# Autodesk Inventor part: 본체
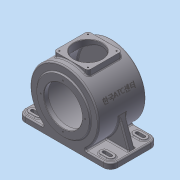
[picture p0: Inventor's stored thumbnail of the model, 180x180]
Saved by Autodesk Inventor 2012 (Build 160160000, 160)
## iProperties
Created: 2015-06
Part Number: 본체
Material: 알루미늄-6061
Document SubType Name: Modeling
Designer: Administrator
Density: 2.71 g/cm^3
Mass: 3293.83 g
Surface Area: 2306.13 cm^2
Volume: 1215.43 cm^3
Author: Administrator
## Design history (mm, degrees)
sketch "스케치1"
  geometry: C1 r 85 at (0, 0); 1 further point
  constraints: 1 centre point, 1 coincident
  dimensions: "d0" = 170 diameter of C1
extrude "돌출1" new body sketch "스케치1" stored distance "d1" = 118; taper "d2" = 0 deg
feature "쉘1" dims "d4" = 8
node "작업 평면11"
sketch "스케치3"
  geometry: C1 r 65 at (0, 0); 1 further point
  constraints: 1 centre point, 1 coincident
  dimensions: "d8" = 130 diameter of C1
sketch "스케치4"
  geometry: C1 r 31 at (0, 0); 1 further point
  constraints: 1 centre point, 1 coincident
  dimensions: "d20" = 62 diameter of C1
extrude "돌출4" join sketch "스케치4" distance "d21" = 3.5; taper "d22" = 0 deg
feature "면 기울기1" dims angle "d41" = 25 deg
node "작업 평면2"
  node "작업 평면1"
sketch "스케치5"
  geometry: L1 (-35.5, 42.5)-(35.5, 42.5); L2 (42.5, 35.5)-(42.5, -35.5); L3 (35.5, -42.5)-(-35.5, -42.5); L4 (-42.5, -35.5)-(-42.5, 35.5); L5 (-42.5, -42.5)-(42.5, 42.5); A1 r 7 centre (-35.5, 35.5) between (-35.5, 42.5) and (-42.5, 35.5); A2 r 7 centre (35.5, 35.5) between (42.5, 35.5) and (35.5, 42.5); A3 r 7 centre (35.5, -35.5) between (35.5, -42.5) and (42.5, -35.5); A4 r 7 centre (-35.5, -35.5) between (-42.5, -35.5) and (-35.5, -42.5); 4 further points
  constraints: 10 end point, 8 point on circle, 8 point on line, 8 tangent, 4 centre point, 3 equal radius, 2 parallel, 1 coincident, 1 horizontal, 1 midpoint, 1 perpendicular
  dimensions: "d44" = 85 distance of point (42.5, -42.5) L5.start; "d45" = 85 distance of L5.start point (-42.5, 42.5); "d46" = 7 radius of A1
extrude "돌출5" join sketch "스케치5" stored distance "d47" = 3.5; taper "d48" = 0 deg
sketch "스케치6"
  geometry: C1 r 35 at (0, 0); 1 further point
  constraints: 1 centre point, 1 coincident
  dimensions: "d49" = 70 diameter of C1
extrude "돌출6" cut sketch "스케치6" stored distance "d50" = 3.5; taper "d51" = 0 deg
sketch "스케치7"
  geometry: A1 r 7 centre (-35.5, 35.5) between (-35.5, 42.5) and (-42.5, 35.5) reference; A2 r 7 centre (-35.5, -35.5) between (-42.5, -35.5) and (-35.5, -42.5) reference; A3 r 7 centre (35.5, -35.5) between (35.5, -42.5) and (42.5, -35.5) reference; A4 r 7 centre (35.5, 35.5) between (42.5, 35.5) and (35.5, 42.5) reference; 5 further points
  constraints: 4 coincident
  dimensions: "d52" = 71 distance of point (35.5, 35.5) point (-35.5, 35.5) (derived); "d53" = 71 distance of point (-35.5, -35.5) point (-35.5, 35.5) (derived)
hole "구멍4" sketch "스케치7" at (-35.5, 35.5), (35.5, 35.5), (35.5, -35.5), (-35.5, -35.5) diameter "d54" = 3.242; stored, may be unused: countersink angle "d58" = 90 deg, drill point angle "d60" = 118 deg; dims "d55" = 10, "d56" = 4, "d57" = 2, "d59" = 13
node "작업 평면9"
node "작업 평면3"
node "작업 평면12"
sketch "스케치11"
  geometry: L1 (-59, -71)-(59, -71); L2 (59, -71)-(59, -85); L3 (59, -85)-(-59, -85); L4 (-59, -85)-(-59, -71); 2 further points
  constraints: 8 end point, 2 parallel, 1 horizontal, 1 midpoint, 1 perpendicular
  dimensions: "d83" = 14 distance of L1.end L2.end; "d84" = 118 distance of L2.end L3.end; "d98" = 85 distance from line of L3 point (0, 0)
extrude "돌출9" join sketch "스케치11" stored distance "d86" = 10; taper "d87" = 0 deg
sketch "스케치13"
  geometry: C1 r 65 at (0, 0); 1 further point
  constraints: 1 centre point, 1 coincident
  dimensions: "d101" = 130 diameter of C1
extrude "돌출13" join sketch "스케치13" distance "d102" = 3; taper "d103" = 0 deg
sketch "스케치8"
  geometry: 5 further points
  dimensions: "d63" = 110 distance of point (0, 55) point (0, -55); "d64" = 110 distance of point (55, 0) point (-55, 0); "d104" = 55 distance of point (0, 0) point (55, 0); "d105" = 55 distance of point (0, 55) point (0, 0)
hole "구멍5" sketch "스케치8" at (0, 55), (-55, 0), (55, 0), (0, -55) diameter "d65" = 3.242; stored, may be unused: countersink angle "d69" = 90 deg, drill point angle "d71" = 118 deg; dims "d66" = 10, "d67" = 4, "d68" = 2, "d70" = 11
extrude "돌출11" join sketch "스케치3" distance "d90" = 13; taper "d91" = 0 deg
node "작업 평면13"
sketch "스케치12"
  geometry: L1 (59, -71)-(-59, -71); L2 (-59, -71)-(-59, -85); L3 (-59, -85)-(59, -85); L4 (59, -85)-(59, -71); 2 further points
  constraints: 8 end point, 2 parallel, 1 horizontal, 1 midpoint, 1 perpendicular, 1 vertical alignment
  dimensions: "d93" = 118 distance of L2.end L3.end; "d94" = 14 distance of L3.end L1.start; "d95" = 85 distance from line of L3 point (0, 0)
extrude "돌출12" join sketch "스케치12" stored distance "d96" = 13; taper "d97" = 0 deg
fillet "모깎기2" dims "d107" = 18
sketch "스케치14"
  geometry: L1 (-34, 9)-(-18, 9); L2 (-18, 27)-(-34, 27); A1 r 9 centre (-18, 18) between (-18, 9) and (-18, 27); A2 r 9 centre (-34, 18) between (-34, 27) and (-34, 9); A3 r 18 centre (-18, 18) between (-18, 0) and (0, 18) reference; 1 further point
  constraints: 4 end point, 4 point on circle, 4 tangent, 2 centre point, 1 coincident, 1 horizontal, 1 parallel
  dimensions: "d108" = 18 distance between parallel lines of L1 L2; "d109" = 16 distance of A2.centre A1.centre
extrude "돌출14" join sketch "스케치14" distance "d110" = 3; taper "d111" = 0 deg
sketch "스케치15"
  geometry: L1 (-34, 27)-(-18, 27) reference; L2 (-18, 9)-(-34, 9) reference; L3 (-18, 14)-(-34, 14); L4 (-34, 22)-(-18, 22); A1 r 9 centre (-18, 18) between (-18, 9) and (-18, 27) reference; A2 r 9 centre (-34, 18) between (-34, 27) and (-34, 9) reference; A3 r 4 centre (-18, 18) between (-18, 14) and (-18, 22); A4 r 4 centre (-34, 18) between (-34, 22) and (-34, 14); 1 further point
  constraints: 4 end point, 4 point on circle, 2 centre point, 3 other
  dimensions: "d112" = 24 dimension on A3 A4
extrude "돌출15" cut sketch "스케치15" stored distance "d113" = 3; taper "d114" = 0 deg
fillet "모깎기6" dims "d142" = 3
sketch "스케치16"
  geometry: L1 (-109, -71)-(-84.87, -4.703); L2 (-115, -74)-(-115, -85) reference; L3 (-106, -71)-(-97, -71) reference; A1 r 85 centre (0, 0) between (46.733, -71) and (-46.733, -71) reference; 1 further point
  constraints: 2 end point, 1 point on circle
  dimensions: "d140" = 6 distance from line of L1.start L2; "d148" = 110 deg angle of L3 L1
feature "리브1" sketch "스케치16" dims "d121" = 1, "d122" = 15, "d123" = 0, "d124" = 0, "d125" = 1, "d126" = 1
fillet "모깎기4" dims "d131" = 3
sketch "스케치19"
  geometry: C1 r 47.5 at (0, 0); 1 further point
  constraints: 1 centre point, 1 coincident
  dimensions: "d143" = 95 diameter of C1
extrude "돌출17" cut sketch "스케치19" distance "d144" = 11; taper "d145" = 0 deg
node "작업 평면16"
node "작업 평면17"
sketch "스케치18"
  geometry: L1 (-41, 7)-(41, 7); L2 (41, 7)-(41, -7); L3 (41, -7)-(-41, -7); L4 (-41, -7)-(-41, 7); L5 (-41, -7)-(41, 7); 2 further points
  constraints: 2 end point, 1 coincident, 1 midpoint, 1 vertical, 2 other
  dimensions: "d135" = 82 distance of L2.end L3.end; "d136" = 14 distance of L3.end L1.start
feature "엠보싱1" sketch "스케치18" dims "d137" = 0.5, "d138" = 0
fillet "모깎기7" dims "d146" = 3
chamfer "모따기1" distance "d149" = 1; stored, may be unused: second distance "d150" = 2, angle "d151" = 45 deg
fillet "모깎기8" dims "d152" = 3
fillet "모깎기10" dims "d154" = 3
hole "구멍6" diameter "d162" = 47; stored, may be unused: countersink angle "d166" = 90 deg, drill point angle "d168" = 0 deg; dims "d160" = 10, "d161" = 10, "d163" = 6, "d164" = 4, "d165" = 2, "d167" = 14
hole "구멍7" diameter "d171" = 30; stored, may be unused: countersink angle "d175" = 90 deg, drill point angle "d177" = 0 deg; dims "d169" = 10, "d170" = 10, "d172" = 6, "d173" = 4, "d174" = 2, "d176" = 3
chamfer "모따기2" distance "d178" = 1; stored, may be unused: second distance "d179" = 2, angle "d180" = 45 deg
fillet "모깎기12" dims "d181" = 3, "d182" = 0.3
fillet "모깎기13" dims "d183" = 3
node "솔리드1"
pattern_linear "직사각형 패턴1" dims "d117" = 82, "d120" = 178
mirror "대칭1"
other parameters: "d42" = 3, "d92" = -115, "d134" = 65 deg
